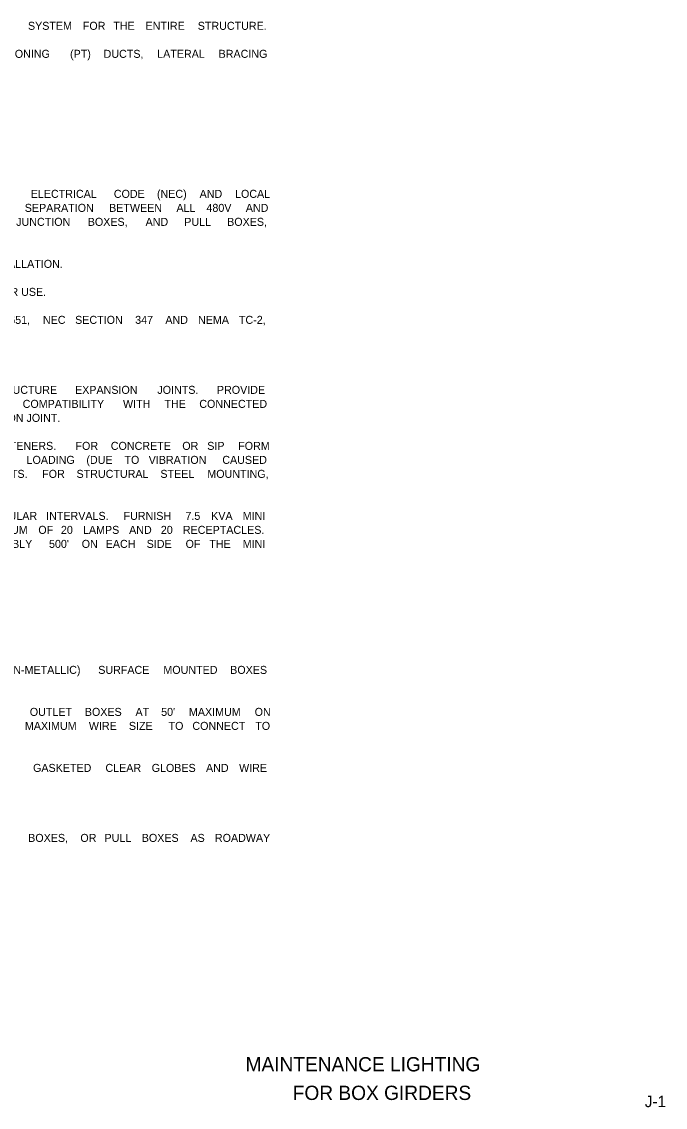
# Model space of a CAD drawing. Extents: x 3080 to 3865, y -34 to 465.
# Drawn here: x 3583.6 to 3864.9, y -21.3 to 453.6 of the extents above; entities that cross this region are included whole.
import ezdxf

# ---------------------------------------------------------------- set-up
doc = ezdxf.new("R2010")
doc.units = 0
for name, color, linetype in [('Miscellaneous4', 7, 'Continuous'), ('TextNotes', 7, 'Continuous'), ('TextShtNo', 7, 'Continuous')]:
    doc.layers.add(name, color=color, linetype=linetype)

msp = doc.modelspace()

# ---------------------------------------------------------------- texts
at = {"layer": 'Miscellaneous4'}
for s, p in [('MAINTENANCE LIGHTING', (3681.44, -5.58)), ('FOR BOX GIRDERS', (3702.07, -18.08))]:
    msp.add_text(s, height=6.25, rotation=360, dxfattribs=at).set_placement(p)
at = {"layer": 'TextNotes'}
for s, p in [('SYSTEM ', (3586.3, 450.07)), ('FOR ', (3610.29, 450.07)), ('THE ', (3623.6, 450.07)), ('ENTIRE ', (3637.71, 450.07)), ('STRUCTURE. ', (3660.54, 450.07)), ('POST-TENSIONING ', (3552.47, 437.82)), ('(PT) ', (3604.71, 437.82)), ('DUCTS, ', (3619.38, 437.82)), ('LATERAL ', (3642.81, 437.82)), ('BRACING ', (3669.66, 437.82)), ('ELECTRICAL ', (3587.52, 376.57)), ('CODE ', (3623.84, 376.57)), ('(NEC) ', (3642.7, 376.57)), ('AND ', (3661.35, 376.57)), ('LOCAL ', (3676.84, 376.57)), ('SEPARATION ', (3584.91, 370.44)), ('BETWEEN ', (3621.78, 370.44)), ('ALL ', (3651.22, 370.44)), ('480V ', (3664.34, 370.44)), ('AND ', (3681.54, 370.44)), ('JUNCTION ', (3581.16, 364.32)), ('BOXES, ', (3612.45, 364.32)), ('AND ', (3637.73, 364.32)), ('PULL ', (3654.65, 364.32)), ('BOXES, ', (3673.39, 364.32)), ('FURNISH ALL LABOR, EQUIPMENT, MATERIALS, AND INCIDENTALS REQUIRED FOR A COMPLETE AND FUNCTIONAL INSTALLATION.', (3302.73, 345.94)), ('USE ONLY NEW, UNUSED AND UNDERWRITERS LABORATORIES (UL) LISTED EQUIPMENT AND MATERIALS FOR OUTDOOR USE.', (3302.73, 333.69)), ('651, ', (3578.12, 321.44)), ('NEC ', (3592.85, 321.44)), ('SECTION ', (3606.93, 321.44)), ('347 ', (3633.19, 321.44)), ('AND ', (3646.38, 321.44)), ('NEMA ', (3660.66, 321.44)), ('TC-2, ', (3678.54, 321.44)), ('STRUCTURE ', (3570.2, 290.82)), ('EXPANSION ', (3606.89, 290.82)), ('JOINTS. ', (3642.88, 290.82)), ('PROVIDE ', (3668.92, 290.82)), ('COMPATIBILITY ', (3583.99, 284.69)), ('WITH ', (3627.86, 284.69)), ('THE ', (3645.97, 284.69)), ('CONNECTED ', (3661.21, 284.69)), ('CONDUITS, WATERPROOF, UV PROTECTED AND ALLOWS LONGITUDINAL MOVEMENT EQUAL TO THAT OF THE EXPANSION JOINT.', (3302.73, 278.57)), ('FASTENERS. ', (3569.25, 266.32)), (' FOR ', (3605.79, 266.32)), ('CONCRETE ', (3622.52, 266.32)), ('OR ', (3653.78, 266.32)), ('SIP ', (3664.69, 266.32)), ('FORM ', (3678.22, 266.32)), ('LOADING ', (3585.69, 260.19)), ('(DUE ', (3611.85, 260.19)), ('TO ', (3628.5, 260.19)), ('VIBRATION ', (3639.09, 260.19)), ('CAUSED ', (3671.27, 260.19)), ('DUCTS. ', (3568.72, 254.07)), (' FOR ', (3591.21, 254.07)), ('STRUCTURAL ', (3607.54, 254.07)), ('STEEL ', (3644.2, 254.07)), ('MOUNTING, ', (3664.73, 254.07)), ('REGULAR ', (3567.68, 235.69)), ('INTERVALS. ', (3594.26, 235.69)), ('FURNISH ', (3628.1, 235.69)), ('7.5 ', (3655.15, 235.69)), ('KVA ', (3666.41, 235.69)), ('MINI ', (3680.2, 235.69)), ('MAXIMUM ', (3563.55, 229.57)), ('OF ', (3590.83, 229.57)), ('20 ', (3600.72, 229.57)), ('LAMPS ', (3610.36, 229.57)), ('AND ', (3630.53, 229.57)), ('20 ', (3644.4, 229.57)), ('RECEPTACLES. ', (3654.04, 229.57)), (' PREFERABLY ', (3555.95, 223.44)), ("500' ", (3595.51, 223.44)), ('ON ', (3609.81, 223.44)), ('EACH ', (3620.29, 223.44)), ('SIDE ', (3638.2, 223.44)), ('OF ', (3655.23, 223.44)), ('THE ', (3665.59, 223.44)), ('MINI ', (3680.2, 223.44)), ('(NON-METALLIC) ', (3571.31, 168.32)), ('SURFACE ', (3617.03, 168.32)), ('MOUNTED ', (3645.51, 168.32)), ('BOXES ', (3674.72, 168.32)), ('OUTLET ', (3587.11, 149.94)), ('BOXES ', (3611.17, 149.94)), ('AT ', (3633.32, 149.94)), ("50' ", (3644.53, 149.94)), ('MAXIMUM ', (3656.68, 149.94)), ('ON ', (3685.41, 149.94)), ('MAXIMUM ', (3584.96, 143.82)), ('WIRE ', (3612.93, 143.82)), ('SIZE ', (3630.43, 143.82)), ('TO ', (3647.78, 143.82)), ('CONNECT ', (3658.2, 143.82)), ('TO ', (3685.69, 143.82)), ('GASKETED ', (3588.54, 125.44)), ('CLEAR ', (3620.18, 125.44)), ('GLOBES ', (3640.39, 125.44)), ('AND ', (3664.15, 125.44)), ('WIRE ', (3678.62, 125.44)), ('BOXES, ', (3586.4, 94.82)), ('OR ', (3609.22, 94.82)), ('PULL ', (3619.78, 94.82)), ('BOXES ', (3636.06, 94.82)), ('AS ', (3657.35, 94.82)), ('ROADWAY ', (3668.04, 94.82))]:
    msp.add_text(s, height=3.5, dxfattribs=at).set_placement(p)
at = {"layer": 'TextShtNo'}
msp.add_text('J-1', height=5, dxfattribs=at).set_placement((3855.99, -21.21))

doc.saveas('drawing.dxf')
